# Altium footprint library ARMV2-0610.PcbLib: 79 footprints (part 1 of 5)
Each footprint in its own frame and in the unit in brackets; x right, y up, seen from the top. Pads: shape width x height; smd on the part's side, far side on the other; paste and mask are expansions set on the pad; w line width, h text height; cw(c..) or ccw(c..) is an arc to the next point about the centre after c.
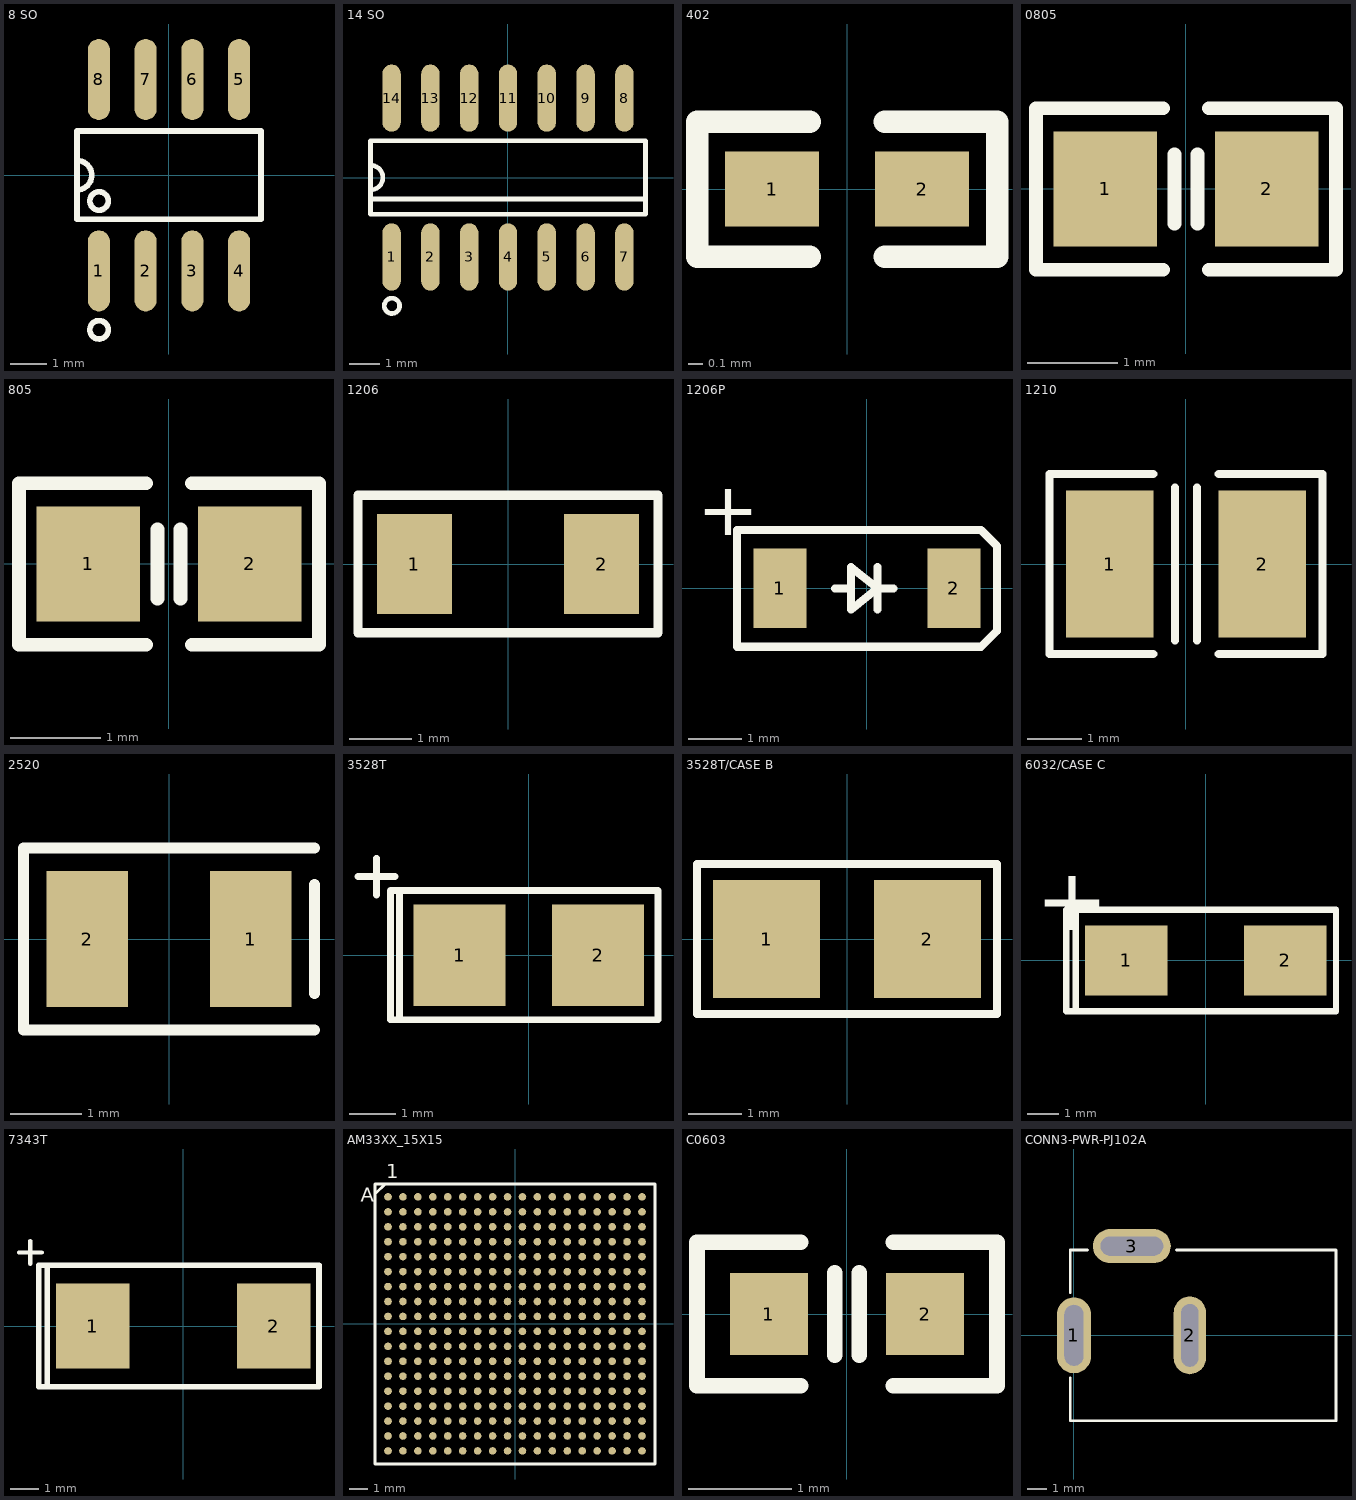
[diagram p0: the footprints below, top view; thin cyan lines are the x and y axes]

## 8 SO [mm]
height 1.75
pads (8):
  oval 0.6x2.2 smd: 1(-1.905,-2.6) 2(-0.635,-2.6) 3(0.635,-2.6) 4(1.905,-2.6) 5(1.905,2.6) 6(0.635,2.6) 7(-0.635,2.6) 8(-1.905,2.6)
Top Overlay:
  circle w0.152: c-1.9,-4.2 r0.25
  circle w0.152: c-1.9,-0.7 r0.25
  lines w0.152: -2.5,-0.4 ccw(c-2.5,0) -2.5,0.4 ; -2.5,-1.2 -2.5,1.2 2.5,1.2 2.5,-1.2 -2.5,-1.2

## 14 SO [mm]
pads (14):
  oval 0.6x2.2 smd: 1(-3.81,-2.6) 2(-2.54,-2.6) 3(-1.27,-2.6) 4(0,-2.6) 5(1.27,-2.6) 6(2.54,-2.6) 7(3.81,-2.6) 8(3.81,2.6) 9(2.54,2.6) 10(1.27,2.6) 11(0,2.6) 12(-1.27,2.6) 13(-2.54,2.6) 14(-3.81,2.6)
Top Overlay:
  circle w0.152: c-3.8,-4.2 r0.25
  lines w0.152: -4.5,-0.7 4.5,-0.7 ; -4.495,-0.4 ccw(c-4.495,0) -4.495,0.4 ; -4.5,-1.2 -4.5,1.2 4.5,1.2 4.5,-1.2 -4.5,-1.2

## 402 [mil] "402"
pads (2):
  rect 25x20 smd mask+2: 1(-20,0) 2(20,0)
Top Overlay:
  lines w6: -10,-18 -40,-18 -40,18 -10,18 ; 10,-18 40,-18 40,18 10,18

## 0805 [mil] "805"
pads (2):
  rect 45x50 smd mask+2: 1(-35,0) 2(35,0)
Top Overlay:
  lines w6: -10,-35 -65,-35 -65,35 -10,35 ; -5,-15 -5,15 ; 5,-15 5,15 ; 10,-35 65,-35 65,30 65,35 10,35

## 805 [mil] "805"
pads (2):
  rect 45x50 smd mask+2: 1(-35,0) 2(35,0)
Top Overlay:
  lines w6: -10,-35 -65,-35 -65,35 -10,35 ; -5,-15 -5,15 ; 5,-15 5,15 ; 10,-35 65,-35 65,30 65,35 10,35

## 1206 [mm]
height 0.71
pads (2):
  rect 1.2x1.6 smd: 1(-1.5,0) 2(1.5,0)
Top Overlay:
  lines w0.15: -2.4,-1.1 2.4,-1.1 2.4,1.1 -2.4,1.1 -2.4,-1.1

## 1206P [mm]
pads (2):
  rect 1x1.5 smd: 1(-1.64,0) 2(1.64,0)
Top Overlay:
  lines w0.152: -0.6,0 -0.3,0 ; 0.2,-0.4 0.2,0.4 ; 0.5,0 0.2,0 ; 0.2,0 -0.3,0.4 -0.3,-0.4 0.2,0 ; -2.45,-1.1 -2.45,1.1 2.15,1.1 2.45,0.8 2.45,-0.8 2.15,-1.1 -2.45,-1.1
  text "+" at -3.2,1 h1.02

## 1210 [mm]
height 1.35
pads (2):
  rect 1.6x2.7 smd: 1(-1.4,0) 2(1.4,0)
Top Overlay:
  lines w0.15: -0.6,-1.65 -2.5,-1.65 -2.5,1.65 -0.6,1.65 ; -0.2,-1.4 -0.2,1.4 ; 0.2,-1.4 0.2,1.4 ; 0.6,-1.65 2.5,-1.65 2.5,1.65 0.6,1.65

## 2520 [mil] "2520"
pads (2):
  rect 45x75 smd mask+2: 1(45,0) 2(-45,0)
Top Overlay:
  lines w6: 80,-50 -80,-50 -80,50 80,50 ; 80,-30 80,30

## 3528T [mm]
height 2.1
pads (2):
  rect 2x2.2 smd: 1(-1.5,0) 2(1.5,0)
Top Overlay:
  lines w0.15: -3.7,1.7 -2.9,1.7 ; -3.3,1.3 -3.3,2.1 ; -2.8,-1.4 2.8,-1.4 2.8,1.4 -2.8,1.4 ; -2.8,-1.4 -2.8,1.4 ; -2.8,-1.4 -3,-1.4 -3,1.4 -2.8,1.4

## 3528T/CASE B [mm]
pads (2):
  rect 2x2.2 smd: 1(-1.5,0) 2(1.5,0)
Top Overlay:
  lines w0.15: -2.8,-1.4 2.8,-1.4 2.8,1.4 -2.8,1.4 -2.8,-1.4

## 6032/CASE C [mm]
height 2.8
pads (2):
  rect 2.6x2.2 smd: 1(-2.5,0) 2(2.5,0)
Top Overlay:
  lines w0.2: -4,-1.6 -4.1,-1.6 ; -4.1,-1.6 4.1,-1.6 4.1,1.6 -4.1,1.6 ; -4.1,-1.6 -4.1,1.6 ; -4.1,-1.6 -4.4,-1.6 -4.4,1.6 -4.1,1.6
  text "+" at -5.35,0.95 h2

## 7343T [mm]
height 3.1
pads (2):
  rect 2.6x3 smd: 1(-3.2,0) 2(3.2,0)
Top Overlay:
  lines w0.15: -5.8,2.6 -5,2.6 ; -5.4,2.2 -5.4,3
  lines w0.2: -4.8,-2.15 -5.1,-2.15 -5.1,2.15 -4.8,2.15 ; -4.8,-2.15 -4.1,-2.15 4.8,-2.15 4.8,2.15 -4.8,2.15 ; -4.8,-2.15 -4.8,2.15

## AM33XX_15X15 [mil] "AM33XX_15X15"
height 55.12
pads (324):
  round 16 smd mask+2: A1(-267.72,267.72) A2(-236.22,267.72) A3(-204.72,267.72) A4(-173.23,267.72) A5(-141.73,267.72) A6(-110.24,267.72) A7(-78.74,267.72) A8(-47.24,267.72) A9(-15.75,267.72) A10(15.75,267.72) A11(47.24,267.72) A12(78.74,267.72) A13(110.24,267.72) A14(141.73,267.72) A15(173.23,267.72) A16(204.72,267.72) A17(236.22,267.72) A18(267.72,267.72) B1(-267.72,236.22) B2(-236.22,236.22) B3(-204.72,236.22) B4(-173.23,236.22) B5(-141.73,236.22) B6(-110.24,236.22) B7(-78.74,236.22) B8(-47.24,236.22) B9(-15.75,236.22) B10(15.75,236.22) B11(47.24,236.22) B12(78.74,236.22) B13(110.24,236.22) B14(141.73,236.22) B15(173.23,236.22) B16(204.72,236.22) B17(236.22,236.22) B18(267.72,236.22) C1(-267.72,204.72) C2(-236.22,204.72) C3(-204.72,204.72) C4(-173.23,204.72) C5(-141.73,204.72) C6(-110.24,204.72) C7(-78.74,204.72) C8(-47.24,204.72) C9(-15.75,204.72) C10(15.75,204.72) C11(47.24,204.72) C12(78.74,204.72) C13(110.24,204.72) C14(141.73,204.72) C15(173.23,204.72) C16(204.72,204.72) C17(236.22,204.72) C18(267.72,204.72) D1(-267.72,173.23) D2(-236.22,173.23) D3(-204.72,173.23) D4(-173.23,173.23) D5(-141.73,173.23) D6(-110.24,173.23) D7(-78.74,173.23) D8(-47.24,173.23) D9(-15.75,173.23) D10(15.75,173.23) D11(47.24,173.23) D12(78.74,173.23) D13(110.24,173.23) D14(141.73,173.23) D15(173.23,173.23) D16(204.72,173.23) D17(236.22,173.23) D18(267.72,173.23) E1(-267.72,141.73) E2(-236.22,141.73) E3(-204.72,141.73) E4(-173.23,141.73) E5(-141.73,141.73) E6(-110.24,141.73) E7(-78.74,141.73) E8(-47.24,141.73) E9(-15.75,141.73) E10(15.75,141.73) E11(47.24,141.73) E12(78.74,141.73) E13(110.24,141.73) E14(141.73,141.73) E15(173.23,141.73) E16(204.72,141.73) E17(236.22,141.73) E18(267.72,141.73) F1(-267.72,110.24) F2(-236.22,110.24) F3(-204.72,110.24) F4(-173.23,110.24) F5(-141.73,110.24) F6(-110.24,110.24) F7(-78.74,110.24) F8(-47.24,110.24) F9(-15.75,110.24) F10(15.75,110.24) F11(47.24,110.24) F12(78.74,110.24) F13(110.24,110.24) F14(141.73,110.24) F15(173.23,110.24) F16(204.72,110.24) F17(236.22,110.24) F18(267.72,110.24) G1(-267.72,78.74) G2(-236.22,78.74) G3(-204.72,78.74) G4(-173.23,78.74) G5(-141.73,78.74) G6(-110.24,78.74) G7(-78.74,78.74) G8(-47.24,78.74) G9(-15.75,78.74) G10(15.75,78.74) G11(47.24,78.74) G12(78.74,78.74) G13(110.24,78.74) G14(141.73,78.74) G15(173.23,78.74) G16(204.72,78.74) G17(236.22,78.74) G18(267.72,78.74) H1(-267.72,47.24) H2(-236.22,47.24) H3(-204.72,47.24) H4(-173.23,47.24) H5(-141.73,47.24) H6(-110.24,47.24) H7(-78.74,47.24) H8(-47.24,47.24) H9(-15.75,47.24) H10(15.75,47.24) H11(47.24,47.24) H12(78.74,47.24) H13(110.24,47.24) H14(141.73,47.24) H15(173.23,47.24) H16(204.72,47.24) H17(236.22,47.24) H18(267.72,47.24) J1(-267.72,15.75) J2(-236.22,15.75) J3(-204.72,15.75) J4(-173.23,15.75) J5(-141.73,15.75) J6(-110.24,15.75) J7(-78.74,15.75) J8(-47.24,15.75) J9(-15.75,15.75) J10(15.75,15.75) J11(47.24,15.75) J12(78.74,15.75) J13(110.24,15.75) J14(141.73,15.75) J15(173.23,15.75) J16(204.72,15.75) J17(236.22,15.75) J18(267.72,15.75) K1(-267.72,-15.75) K2(-236.22,-15.75) K3(-204.72,-15.75) K4(-173.23,-15.75) K5(-141.73,-15.75) K6(-110.24,-15.75) K7(-78.74,-15.75) K8(-47.24,-15.75) K9(-15.75,-15.75) K10(15.75,-15.75) K11(47.24,-15.75) K12(78.74,-15.75) K13(110.24,-15.75) K14(141.73,-15.75) K15(173.23,-15.75) K16(204.72,-15.75) K17(236.22,-15.75) K18(267.72,-15.75) L1(-267.72,-47.24) L2(-236.22,-47.24) L3(-204.72,-47.24) L4(-173.23,-47.24) L5(-141.73,-47.24) L6(-110.24,-47.24) L7(-78.74,-47.24) L8(-47.24,-47.24) L9(-15.75,-47.24) L10(15.75,-47.24) L11(47.24,-47.24) L12(78.74,-47.24) L13(110.24,-47.24) L14(141.73,-47.24) L15(173.23,-47.24) L16(204.72,-47.24) L17(236.22,-47.24) L18(267.72,-47.24) M1(-267.72,-78.74) M2(-236.22,-78.74) M3(-204.72,-78.74) M4(-173.23,-78.74) M5(-141.73,-78.74) M6(-110.24,-78.74) M7(-78.74,-78.74) M8(-47.24,-78.74) M9(-15.75,-78.74) M10(15.75,-78.74) M11(47.24,-78.74) M12(78.74,-78.74) M13(110.24,-78.74) M14(141.73,-78.74) M15(173.23,-78.74) M16(204.72,-78.74) M17(236.22,-78.74) M18(267.72,-78.74) N1(-267.72,-110.24) N2(-236.22,-110.24) N3(-204.72,-110.24) N4(-173.23,-110.24) N5(-141.73,-110.24) N6(-110.24,-110.24) N7(-78.74,-110.24) N8(-47.24,-110.24) N9(-15.75,-110.24) N10(15.75,-110.24) N11(47.24,-110.24) N12(78.74,-110.24) N13(110.24,-110.24) N14(141.73,-110.24) N15(173.23,-110.24) N16(204.72,-110.24) N17(236.22,-110.24) N18(267.72,-110.24) P1(-267.72,-141.73) P2(-236.22,-141.73) P3(-204.72,-141.73) P4(-173.23,-141.73) P5(-141.73,-141.73) P6(-110.24,-141.73) P7(-78.74,-141.73) P8(-47.24,-141.73) P9(-15.75,-141.73) P10(15.75,-141.73) P11(47.24,-141.73) P12(78.74,-141.73) P13(110.24,-141.73) P14(141.73,-141.73) P15(173.23,-141.73) P16(204.72,-141.73) P17(236.22,-141.73) P18(267.72,-141.73) R1(-267.72,-173.23) R2(-236.22,-173.23) R3(-204.72,-173.23) R4(-173.23,-173.23) R5(-141.73,-173.23) R6(-110.24,-173.23) R7(-78.74,-173.23) R8(-47.24,-173.23) R9(-15.75,-173.23) R10(15.75,-173.23) R11(47.24,-173.23) R12(78.74,-173.23) R13(110.24,-173.23) R14(141.73,-173.23) R15(173.23,-173.23) R16(204.72,-173.23) R17(236.22,-173.23) R18(267.72,-173.23) T1(-267.72,-204.72) T2(-236.22,-204.72) T3(-204.72,-204.72) T4(-173.23,-204.72) T5(-141.73,-204.72) T6(-110.24,-204.72) T7(-78.74,-204.72) T8(-47.24,-204.72) T9(-15.75,-204.72) T10(15.75,-204.72) T11(47.24,-204.72) T12(78.74,-204.72) T13(110.24,-204.72) T14(141.73,-204.72) T15(173.23,-204.72) T16(204.72,-204.72) T17(236.22,-204.72) T18(267.72,-204.72) U1(-267.72,-236.22) U2(-236.22,-236.22) U3(-204.72,-236.22) U4(-173.23,-236.22) U5(-141.73,-236.22) U6(-110.24,-236.22) U7(-78.74,-236.22) U8(-47.24,-236.22) U9(-15.75,-236.22) U10(15.75,-236.22) U11(47.24,-236.22) U12(78.74,-236.22) U13(110.24,-236.22) U14(141.73,-236.22) U15(173.23,-236.22) U16(204.72,-236.22) U17(236.22,-236.22) U18(267.72,-236.22) V1(-267.72,-267.72) V2(-236.22,-267.72) V3(-204.72,-267.72) V4(-173.23,-267.72) V5(-141.73,-267.72) V6(-110.24,-267.72) V7(-78.74,-267.72) V8(-47.24,-267.72) V9(-15.75,-267.72) V10(15.75,-267.72) V11(47.24,-267.72) V12(78.74,-267.72) V13(110.24,-267.72) V14(141.73,-267.72) V15(173.23,-267.72) V16(204.72,-267.72) V17(236.22,-267.72) V18(267.72,-267.72)
Top Overlay:
  lines w5.91: -295.28,273.62 -273.62,295.28
  lines w6: -295.28,-295.28 -295.28,295.28 295.28,295.28 295.28,-295.28 -295.28,-295.28
  text "1" at -271.65,307.09 h30
  text "A" at -324.8,257.87 h30

## C0603 [mm]
height 0.85
pads (2):
  rect 0.76x0.8 smd: 1(-0.76,0) 2(0.76,0)
Top Overlay:
  lines w0.152: -0.45,-0.7 -1.46,-0.7 -1.46,0.7 -0.45,0.7 ; -0.12,-0.4 -0.12,0.4 ; 0.12,-0.4 0.12,0.4 ; 0.45,-0.7 1.46,-0.7 1.46,0.7 0.45,0.7

## CONN3-PWR-PJ102A [mm] "CONN3-PWR-PJ102A"
pads (3):
  oval 1.8x4 hole 1 slot 3.2 at 90 deg mask+0.051: 1(0,0)
  oval 1.7x4.1 hole 0.9 slot 3.3 at 90 deg mask+0.051: 2(6.1,0)
  oval 4.1x1.8 hole 1 slot 3.3 at 0 deg mask+0.051: 3(3.05,4.7)
Top Overlay:
  lines w0.15: -0.2,-2.25 -0.2,-4.5 13.8,-4.5 13.8,4.5 5.403,4.5 ; -0.2,2.25 -0.2,4.5 0.704,4.5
